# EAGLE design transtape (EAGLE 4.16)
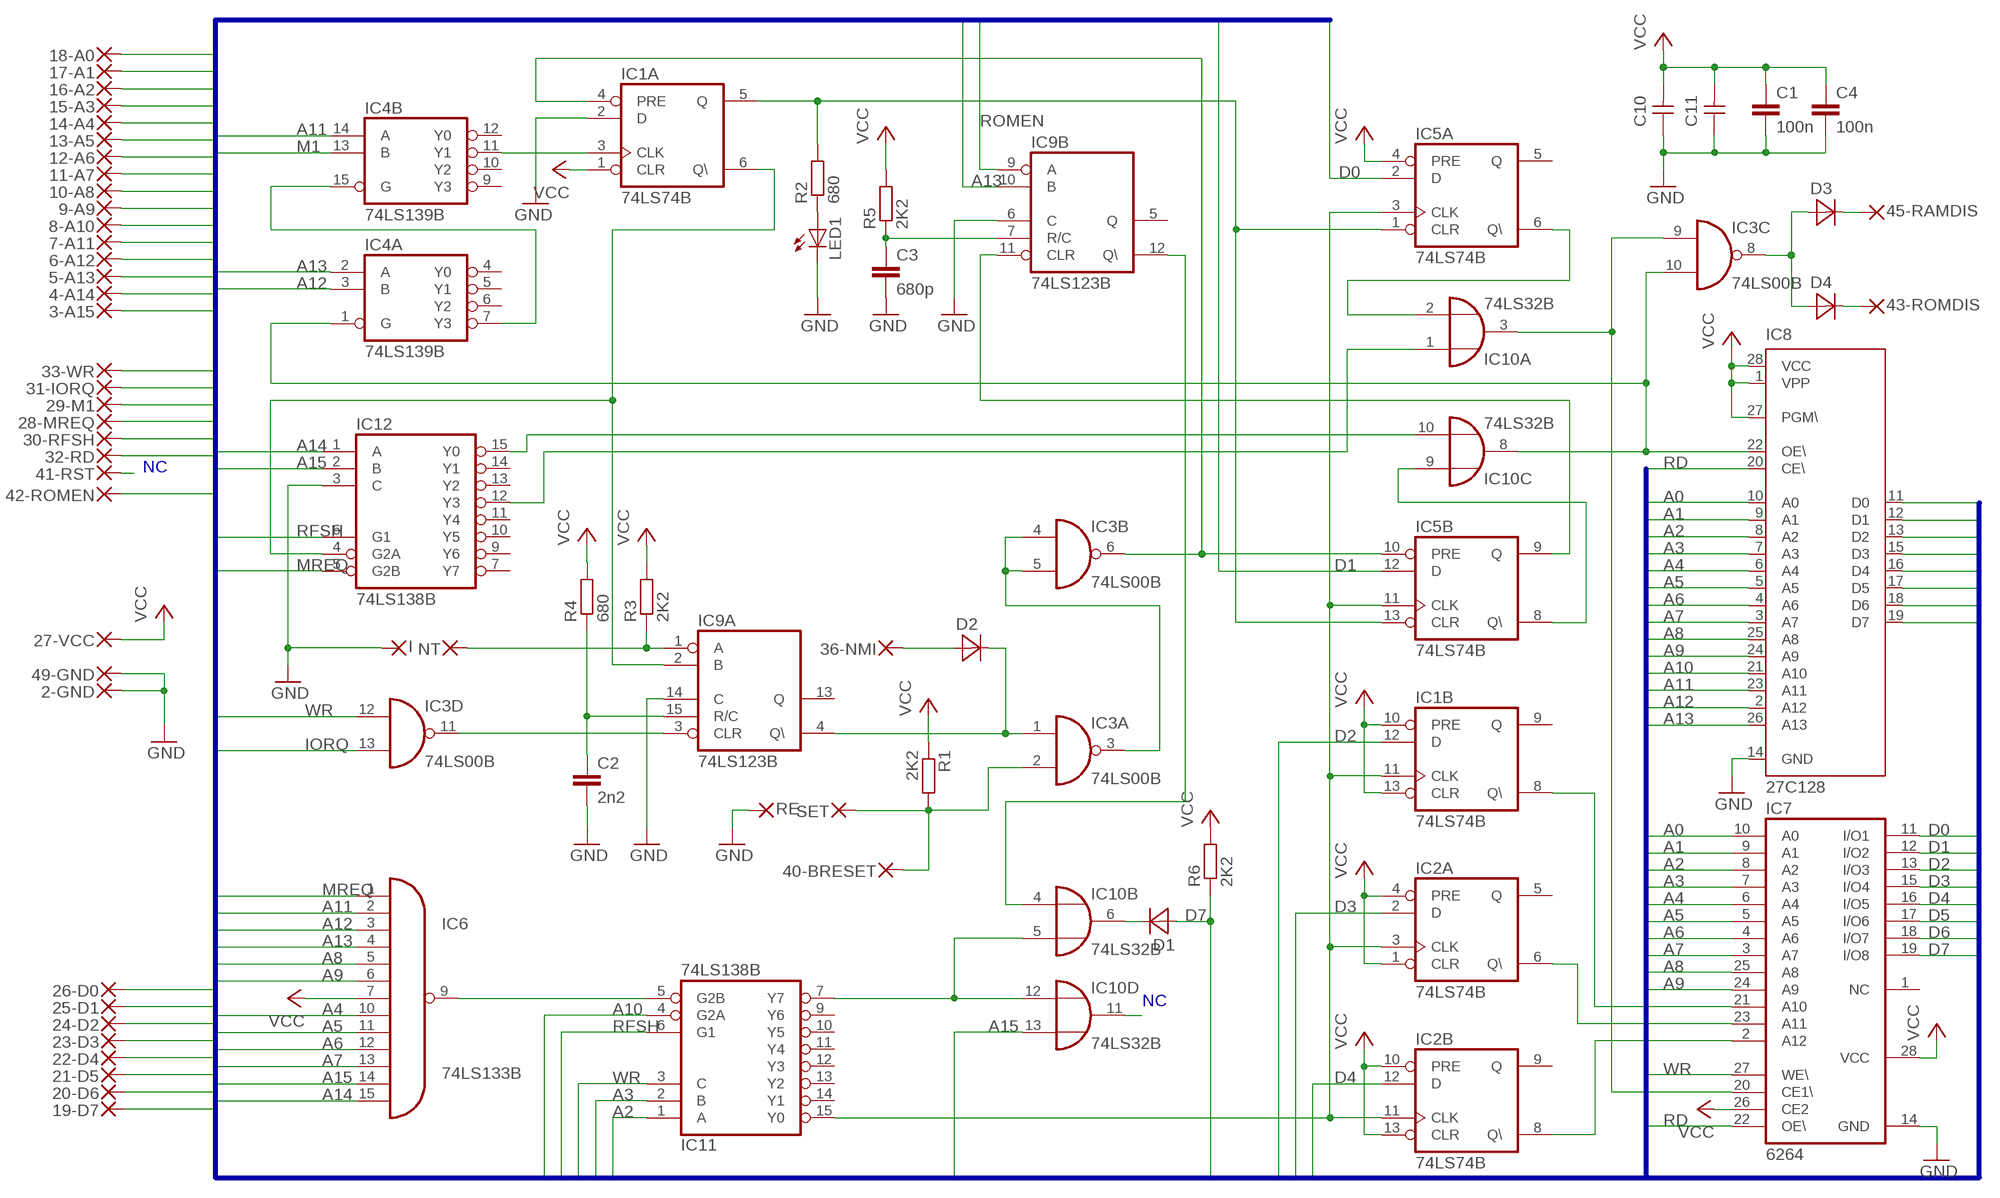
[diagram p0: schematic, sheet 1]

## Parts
2-GND  1,27-REDONDO0.8  [1,27/0,8-REDONDO]
3-A15  1,27-REDONDO0.8  [1,27/0,8-REDONDO]
4-A14  1,27-REDONDO0.8  [1,27/0,8-REDONDO]
5-A13  1,27-REDONDO0.8  [1,27/0,8-REDONDO]
6-A12  1,27-REDONDO0.8  [1,27/0,8-REDONDO]
7-A11  1,27-REDONDO0.8  [1,27/0,8-REDONDO]
8-A10  1,27-REDONDO0.8  [1,27/0,8-REDONDO]
9-A9  1,27-REDONDO0.8  [1,27/0,8-REDONDO]
10-A8  1,27-REDONDO0.8  [1,27/0,8-REDONDO]
11-A7  1,27-REDONDO0.8  [1,27/0,8-REDONDO]
12-A6  1,27-REDONDO0.8  [1,27/0,8-REDONDO]
13-A5  1,27-REDONDO0.8  [1,27/0,8-REDONDO]
14-A4  1,27-REDONDO0.8  [1,27/0,8-REDONDO]
15-A3  1,27-REDONDO0.8  [1,27/0,8-REDONDO]
16-A2  1,27-REDONDO0.8  [1,27/0,8-REDONDO]
17-A1  1,27-REDONDO0.8  [1,27/0,8-REDONDO]
18-A0  1,27-REDONDO0.8  [1,27/0,8-REDONDO]
19-D7  1,27-REDONDO0.8  [1,27/0,8-REDONDO]
20-D6  1,27-REDONDO0.8  [1,27/0,8-REDONDO]
21-D5  1,27-REDONDO0.8  [1,27/0,8-REDONDO]
22-D4  1,27-REDONDO0.8  [1,27/0,8-REDONDO]
23-D3  1,27-REDONDO0.8  [1,27/0,8-REDONDO]
24-D2  1,27-REDONDO0.8  [1,27/0,8-REDONDO]
25-D1  1,27-REDONDO0.8  [1,27/0,8-REDONDO]
26-D0  1,27-REDONDO0.8  [1,27/0,8-REDONDO]
27-VCC  1,27-REDONDO0.8  [1,27/0,8-REDONDO]
28-MREQ  1,27-REDONDO0.8  [1,27/0,8-REDONDO]
29-M1  1,27-REDONDO0.8  [1,27/0,8-REDONDO]
30-RFSH  1,27-REDONDO0.8  [1,27/0,8-REDONDO]
31-IORQ  1,27-REDONDO0.8  [1,27/0,8-REDONDO]
32-RD  1,27-REDONDO0.8  [1,27/0,8-REDONDO]
33-WR  1,27-REDONDO0.8  [1,27/0,8-REDONDO]
36-NMI  1,27-REDONDO0.8  [1,27/0,8-REDONDO]
40-BRESET  1,27-REDONDO0.8  [1,27/0,8-REDONDO]
41-RST  1,27-REDONDO0.8  [1,27/0,8-REDONDO]
42-ROMEN  1,27-REDONDO0.8  [1,27/0,8-REDONDO]
43-ROMDIS  1,27-REDONDO0.8  [1,27/0,8-REDONDO]
45-RAMDIS  1,27-REDONDO0.8  [1,27/0,8-REDONDO]
49-GND  1,27-REDONDO0.8  [1,27/0,8-REDONDO]
C1  100n  C-EU050-025X075  [C050-025X075]
C2  2n2  C-EU050-025X075  [C050-025X075]
C3  680p  C-EU050-025X075  [C050-025X075]
C4  100n  C-EU075-032X103  [C075-032X103]
C10  CAPNP-7,5  [C-7,5]
C11  CAPNP-7,5  [C-7,5]
D1  DIODE-5  [D-5]
D2  DIODE-7,5  [D-7,5]
D3  DIODE-7,5  [D-7,5]
D4  DIODE-7,5  [D-7,5]
I  1,27-OVALADO0.8  [1,27/0,8]
IC1  74LS74B  [DIL14-B]
IC2  74LS74B  [DIL14-B]
IC3  74LS00B  [DIL14-B]
IC4  74LS139B  [DIL16-B]
IC5  74LS74B  [DIL14-B]
IC6  74LS133B  [DIL16-B]
IC7  6264  4364CB  [DIL28-6B]
IC8  27C128  27128B  [DIL28-6B]
IC9  74LS123B  [DIL16-B]
IC10  74LS32B  [DIL14-B]
IC11  74LS138B  [DIL16-B]
IC12  74LS138B  [DIL16-B]
LED1  LED3MM  [LED3MM]
NT  1,27-OVALADO0.8  [1,27/0,8]
R1  2K2  R-EU_0207/10  [0207/10]
R2  680  R-EU_0207/10  [0207/10]
R3  2K2  R-EU_0207/10  [0207/10]
R4  680  R-EU_0207/10  [0207/10]
R5  2K2  R-EU_0207/10  [0207/10]
R6  2K2  R-EU_0207/7  [0207/7]
RE  1,27-OVALADO0.8  [1,27/0,8]
SET  1,27-OVALADO0.8  [1,27/0,8]

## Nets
A0: 18-A0.1(P) IC7.10(A0) IC8.10(A0)
A1: 17-A1.1(P) IC7.9(A1) IC8.9(A1)
A2: 16-A2.1(P) IC7.8(A2) IC8.8(A2) IC11.1(A)
A3: 15-A3.1(P) IC7.7(A3) IC8.7(A3) IC11.2(B)
A4: 14-A4.1(P) IC6.10(I7) IC7.6(A4) IC8.6(A4)
A5: 13-A5.1(P) IC6.11(I8) IC7.5(A5) IC8.5(A5)
A6: 12-A6.1(P) IC6.12(I9) IC7.4(A6) IC8.4(A6)
A7: 11-A7.1(P) IC6.13(I10) IC7.3(A7) IC8.3(A7)
A8: 10-A8.1(P) IC6.5(I4) IC7.25(A8) IC8.25(A8)
A9: 9-A9.1(P) IC6.6(I5) IC7.24(A9) IC8.24(A9)
A10: 8-A10.1(P) IC8.21(A10) IC11.4(G2A)
A11: 7-A11.1(P) IC4.14(B:A) IC6.2(I1) IC8.23(A11)
A12: 6-A12.1(P) IC4.3(A:B) IC6.3(I2) IC8.2(A12)
A13: 5-A13.1(P) IC4.2(A:A) IC6.4(I3) IC8.26(A13) IC9.10(B:B)
A14: 4-A14.1(P) IC6.15(I12) IC12.1(A)
A15: 3-A15.1(P) IC6.14(I11) IC10.13(D:I1) IC12.2(B)
BRESET: 40-BRESET.1(P) IC3.2(A:I1) R1.2 SET.1(P)
D0: 26-D0.1(P) IC5.2(A:D) IC7.11(I/O1) IC8.11(D0)
D1: 25-D1.1(P) IC5.12(B:D) IC7.12(I/O2) IC8.12(D1)
D2: 24-D2.1(P) IC1.12(B:D) IC7.13(I/O3) IC8.13(D2)
D3: 23-D3.1(P) IC2.2(A:D) IC7.15(I/O4) IC8.15(D3)
D4: 22-D4.1(P) IC2.12(B:D) IC7.16(I/O5) IC8.16(D4)
D5: 21-D5.1(P) IC7.17(I/O6) IC8.17(D5)
D6: 20-D6.1(P) IC7.18(I/O7) IC8.18(D6)
D7: 19-D7.1(P) D1.A IC7.19(I/O8) IC8.19(D7) R6.1
GND: 2-GND.1(P) 49-GND.1(P) C1.2 C2.2 C3.2 C4.2 C10.1 C11.1 I.1(P) IC1.2(A:D) IC7.14(GND) IC8.14(GND) IC9.6(B:C) IC9.14(A:C) IC12.3(C) LED1.K(C) RE.1(P)
IORQ: 31-IORQ.1(P) IC3.13(D:I1)
M1: 29-M1.1(P) IC4.13(B:B)
MREQ: 28-MREQ.1(P) IC6.1(I0) IC12.5(G2B)
N$5: IC3.10(C:I1) IC4.1(A:G) IC8.22(OE\) IC10.8(C:O)
N$12: 41-RST.1(P)
N$27: IC10.11(D:O)
N$33: IC10.1(A:I0) IC12.12(Y3)
N$34: IC1.6(A:Q\) IC9.2(A:B) IC12.4(G2A)
N$35: IC9.1(A:A) NT.1(P) R3.1
N$36: IC10.10(C:I1) IC12.15(Y0)
N$37: IC1.11(B:CLK) IC2.3(A:CLK) IC2.11(B:CLK) IC5.3(A:CLK) IC5.11(B:CLK) IC11.15(Y0)
N$38: IC6.9(O) IC11.5(G2B)
N$39: IC10.5(B:I1) IC10.12(D:I0) IC11.7(Y7)
N$40: IC5.8(B:Q\) IC10.9(C:I0)
N$41: IC5.6(A:Q\) IC10.2(A:I1)
N$42: IC3.9(C:I0) IC7.20(CE1\) IC10.3(A:O)
N$43: IC9.12(B:Q\) IC10.4(B:I0)
N$44: D1.C(K) IC10.6(B:O)
N$45: C2.1 IC9.15(A:R/C) R4.1
N$46: C3.1 IC9.7(B:R/C) R5.1
N$47: LED1.A R2.1
N$50: IC5.9(B:Q) IC9.11(B:CLR)
N$51: D2.2(K) IC3.1(A:I0) IC9.4(A:Q\)
N$52: IC3.11(D:O) IC9.3(A:CLR)
N$53: IC1.5(A:Q) IC5.1(A:CLR) IC5.13(B:CLR) R2.2
N$54: IC1.4(A:PRE) IC3.6(B:O) IC5.10(B:PRE)
N$57: IC1.3(A:CLK) IC4.11(B:Y1)
N$58: IC1.8(B:Q\) IC7.21(A10)
N$59: IC2.6(A:Q\) IC7.23(A11)
N$60: IC2.8(B:Q\) IC7.2(A12)
N$62: IC3.3(A:O) IC3.4(B:I0) IC3.5(B:I1)
N$64: D3.1(A) D4.1(A) IC3.8(C:O)
N$66: IC4.7(A:Y3) IC4.15(B:G)
N$72: 36-NMI.1(P) D2.1(A)
RAMDIS: 45-RAMDIS.1(P) D3.2(K)
RD: 32-RD.1(P) IC7.22(OE\) IC8.20(CE\)
RFSH: 30-RFSH.1(P) IC11.6(G1) IC12.6(G1)
ROMDIS: 43-ROMDIS.1(P) D4.2(K)
ROMEN: 42-ROMEN.1(P) IC9.9(B:A)
VCC: 27-VCC.1(P) C1.1 C4.1 C10.2 C11.2 IC1.1(A:CLR) IC1.10(B:PRE) IC1.13(B:CLR) IC2.1(A:CLR) IC2.4(A:PRE) IC2.10(B:PRE) IC2.13(B:CLR) IC5.4(A:PRE) IC6.7(I6) IC7.26(CE2) IC7.28(VCC) IC8.1(VPP) IC8.27(PGM\) IC8.28(VCC) R1.1 R3.2 R4.2 R5.2 R6.2
WR: 33-WR.1(P) IC3.12(D:I0) IC7.27(WE\) IC11.3(C)
Unconnected: IC1.9(B:Q) IC2.5(A:Q) IC2.9(B:Q) IC4.4(A:Y0) IC4.5(A:Y1) IC4.6(A:Y2) IC4.9(B:Y3) IC4.10(B:Y2) IC4.12(B:Y0) IC5.5(A:Q) IC7.1(NC) IC9.5(B:Q) IC9.13(A:Q) IC11.9(Y6) IC11.10(Y5) IC11.11(Y4) IC11.12(Y3) IC11.13(Y2) IC11.14(Y1) IC12.7(Y7) IC12.9(Y6) IC12.10(Y5) IC12.11(Y4) IC12.13(Y2) IC12.14(Y1)

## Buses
A[0..15],RD,WR,IORQ,M1,MREQ,RFSH,D[0..7],ROMEN

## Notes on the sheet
- NC
- NC

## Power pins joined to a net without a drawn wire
GND: IC1.7(P:GND) IC2.7(P:GND) IC3.7(P:GND) IC4.8(P:GND) IC5.7(P:GND) IC6.8(GND) IC9.8(P:GND) IC10.7(P:GND) IC11.8(GND) IC12.8(GND)
VCC: IC1.14(P:VCC) IC2.14(P:VCC) IC3.14(P:VCC) IC4.16(P:VCC) IC5.14(P:VCC) IC6.16(VCC) IC9.16(P:VCC) IC10.14(P:VCC) IC11.16(VCC) IC12.16(VCC)

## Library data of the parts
2-GND 3-A15 4-A14 5-A13 6-A12 7-A11 8-A10 9-A9 10-A8 11-A7 12-A6 13-A5 14-A4 15-A3 16-A2 17-A1 18-A0 19-D7 20-D6 21-D5 22-D4 23-D3 24-D2 25-D1 26-D0 27-VCC 28-MREQ 29-M1 30-RFSH 31-IORQ 32-RD 33-WR 36-NMI 40-BRESET 41-RST 42-ROMEN 43-ROMDIS 45-RAMDIS 49-GND = wirepad2:1,27-REDONDO
C1-C4 = rcl:C-EU: CAPACITOR, European symbol
C10 C11 = discrete2:CAPNP-7,5
D1 = discrete2:DIODE-5
D2-D4 = discrete2:DIODE-7,5
I NT RE SET = wirepad2:1,27-OVALADO
IC1 IC2 IC5 = 74xx-eu2:74*74: Dual D type positive edge triggered FLIP FLOP, preset and clear
IC3 = 74xx-eu2:74*00: Quad 2-input NAND gate
IC4 = 74xx-eu2:74*139: Dual 2-line to 4-line DECODER/DEMULTIPLEXER
IC6 = 74xx-eu2:74*133: 13-input NAND gate
IC7 = memory-nec:4364C: MEMORY
IC8 = microchip:27*128: CMOS EPROM 128 K (16 K x 8)
IC9 = 74xx-eu2:74*123: Retriggerable monostable MULTIVIBRATOR
IC10 = 74xx-eu2:74*32: Quad 2-input OR gate
IC11 IC12 = 74xx-eu2:74*138: 3-line to 8-line DECODER/DEMULTIPLEXER
LED1 = led:LED: LED
R1-R6 = rcl:R-EU_: RESISTOR, European symbol

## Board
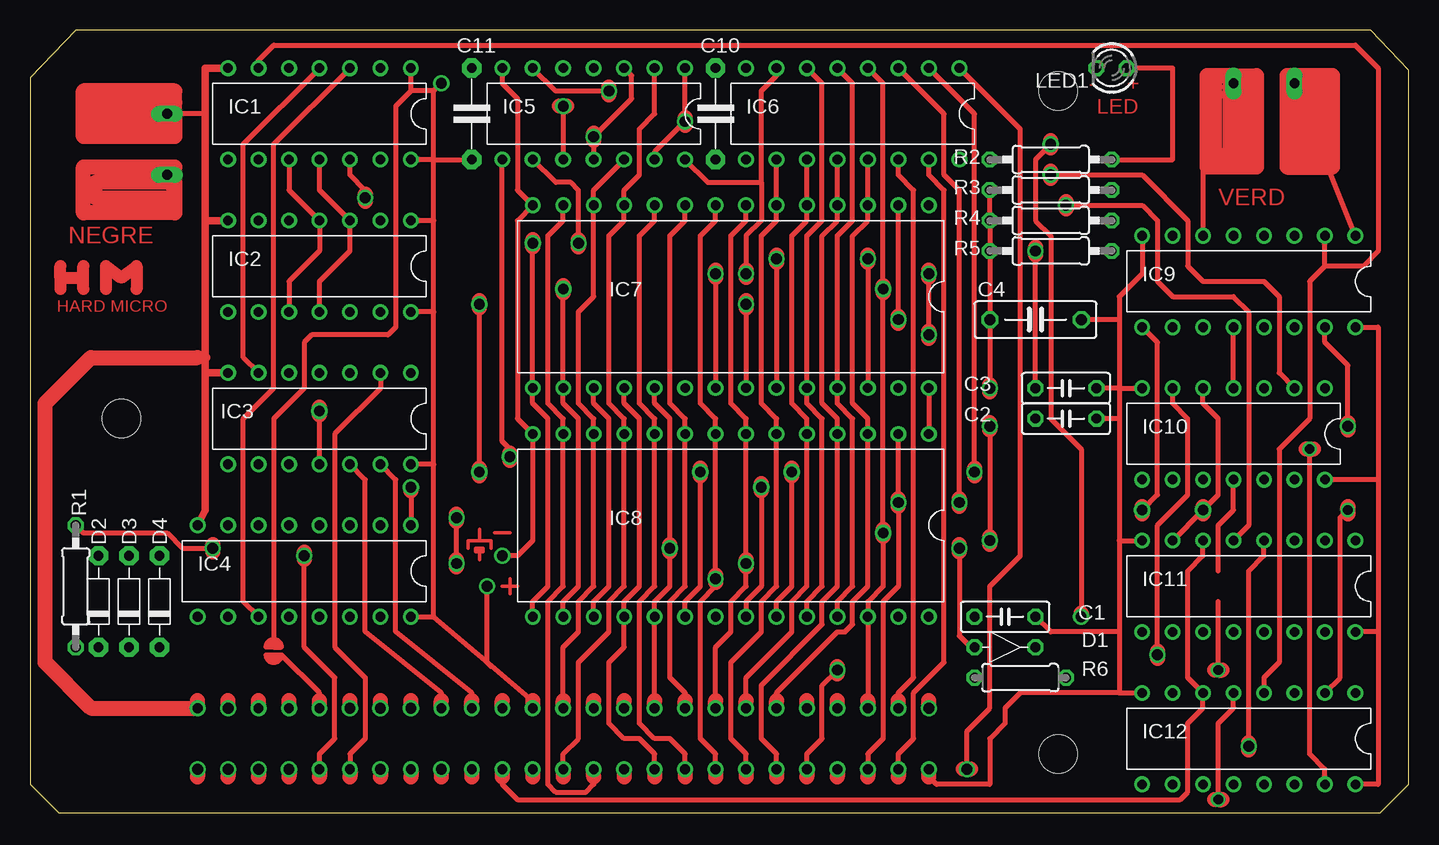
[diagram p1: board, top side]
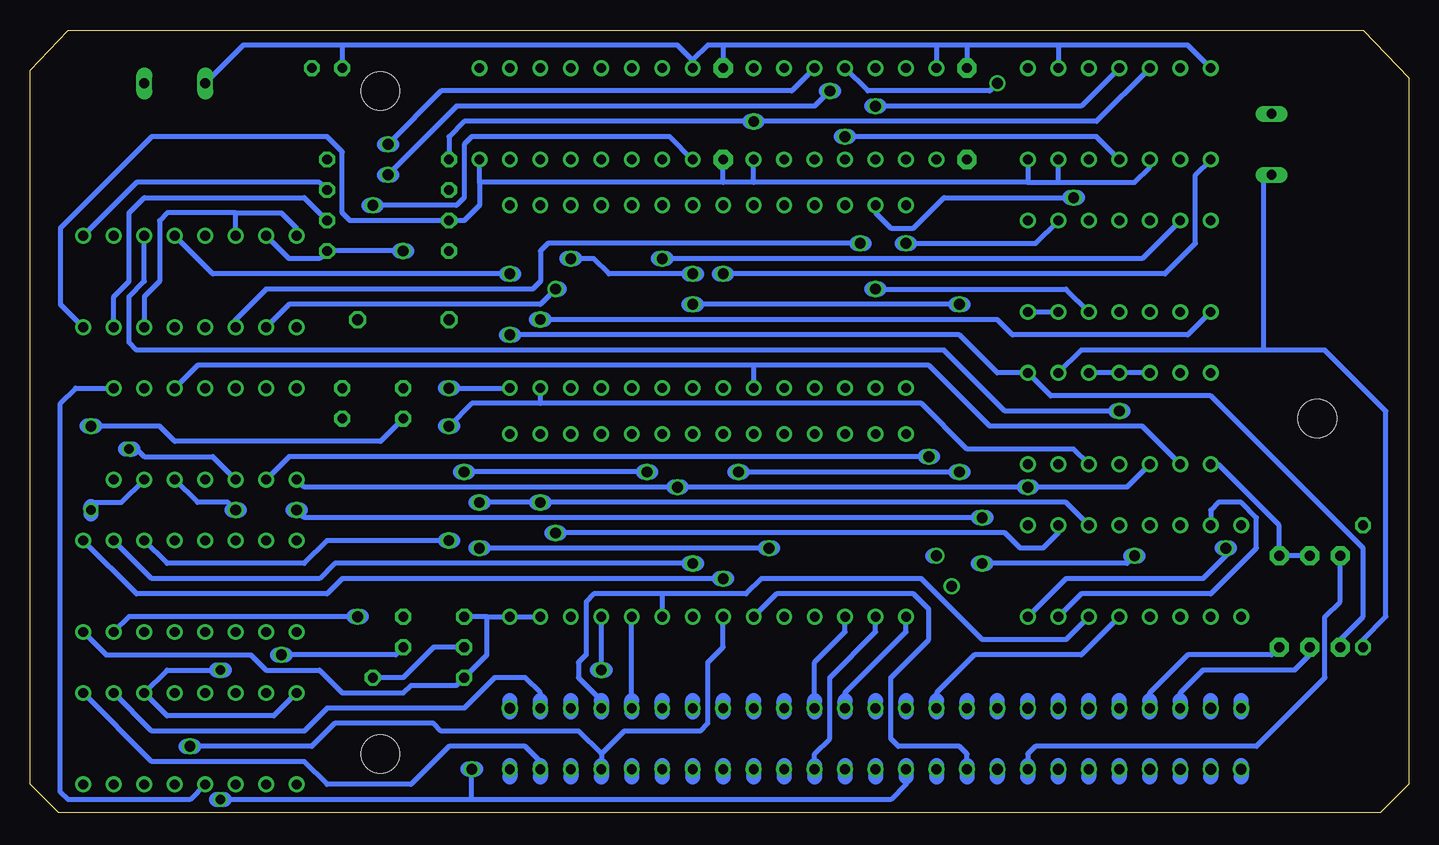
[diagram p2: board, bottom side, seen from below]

Size 114.94 x 65.24 mm. Coordinates in mm from the lower left corner, seen from the top.
Outline: 112.56,0 114.94,2.38 114.92,61.9 114.94,61.9 111.76,65.24 3.81,65.24 0,61.27 0.01,59.99 0,2.38 2.38,0 112.56,0
Copper layers (1*16): Top 0.035mm / dielectric 1.5mm / Bottom 0.035mm
Design rules "default": minimum track width 10mil, minimum drill 24mil, track to track 8mil, track to pad 8mil, pad to pad 8mil, via to via 8mil, smd to smd 8mil, copper to edge 40mil, drill to drill 8mil, minimum pad ring 10mil, minimum via ring 8mil, stop-mask expansion 4mil, vias tented up to drill 0mil, thermal gap 10mil
Holes 3.2 mm at 85.72,4.92 85.72,60.16 7.62,32.86

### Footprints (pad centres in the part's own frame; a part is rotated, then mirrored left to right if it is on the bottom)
1,27/0,8-REDONDO = drill 0.813 pad 1.27 round: 1 0,0
C050-025X075 = drill 0.813 octagon: 1 -2.54,0; 2 2.54,0
C075-032X103 = drill 0.914 octagon: 1 -3.81,0; 2 3.81,0
C-7,5 = drill 0.813 pad 1.6 octagon: 1 -3.81,0; 2 3.81,0
D-5 = drill 0.813 octagon: A -2.54,0; C 2.54,0
D-7,5 = drill 0.813 pad 1.6 octagon: 1 -3.81,0; 2 3.81,0
1,27/0,8 = drill 0.813 long: 1 -1.27,1.27
DIL14-B = drill 0.813 round: 1 -7.62,-3.81; 2 -5.08,-3.81; 3 -2.54,-3.81; 4 0,-3.81; 5 2.54,-3.81; 6 5.08,-3.81; 7 7.62,-3.81; 8 7.62,3.81; 9 5.08,3.81; 10 2.54,3.81; 11 0,3.81; 12 -2.54,3.81; 13 -5.08,3.81; 14 -7.62,3.81
DIL16-B = drill 0.813 round: 1 -8.89,-3.81; 2 -6.35,-3.81; 3 -3.81,-3.81; 4 -1.27,-3.81; 5 1.27,-3.81; 6 3.81,-3.81; 7 6.35,-3.81; 8 8.89,-3.81; 9 8.89,3.81; 10 6.35,3.81; 11 3.81,3.81; 12 1.27,3.81; 13 -1.27,3.81; 14 -3.81,3.81; 15 -6.35,3.81; 16 -8.89,3.81
DIL28-6B = drill 0.8 round: 1 -16.51,-7.62; 2 -13.97,-7.62; 3 -11.43,-7.62; 4 -8.89,-7.62; 5 -6.35,-7.62; 6 -3.81,-7.62; 7 -1.27,-7.62; 8 1.27,-7.62; 9 3.81,-7.62; 10 6.35,-7.62; 11 8.89,-7.62; 12 11.43,-7.62; 13 13.97,-7.62; 14 16.51,-7.62; 15 16.51,7.62; 16 13.97,7.62; 17 11.43,7.62; 18 8.89,7.62; 19 6.35,7.62; 20 3.81,7.62; 21 1.27,7.62; 22 -1.27,7.62; 23 -3.81,7.62; 24 -6.35,7.62; 25 -8.89,7.62; 26 -11.43,7.62; 27 -13.97,7.62; 28 -16.51,7.62
LED3MM = drill 0.813 octagon: A -1.27,0; K 1.27,0
0207/10 = drill 0.813 octagon: 1 -5.08,0; 2 5.08,0
0207/7 = drill 0.813 octagon: 1 -3.81,0; 2 3.81,0

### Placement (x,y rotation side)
2-GND  74.93,3.65 180 top
3-A15  72.39,8.73 0 top
4-A14  72.39,3.65 180 top
5-A13  69.85,8.73 0 top
6-A12  69.85,3.65 180 top
7-A11  67.31,8.73 0 top
8-A10  67.31,3.65 180 top
9-A9  64.77,8.73 0 top
10-A8  64.77,3.65 180 top
11-A7  62.23,8.73 0 top
12-A6  62.23,3.65 180 top
13-A5  59.69,8.73 0 top
14-A4  59.69,3.65 180 top
15-A3  57.15,8.73 0 top
16-A2  57.15,3.65 180 top
17-A1  54.61,8.73 0 top
18-A0  54.61,3.65 180 top
19-D7  52.07,8.73 0 top
20-D6  52.07,3.65 180 top
21-D5  49.53,8.73 0 top
22-D4  49.53,3.65 180 top
23-D3  46.99,8.73 0 top
24-D2  46.99,3.65 180 top
25-D1  44.45,8.73 0 top
26-D0  44.45,3.65 180 top
27-VCC  41.91,8.73 0 top
28-MREQ  41.91,3.65 180 top
29-M1  39.37,8.73 0 top
30-RFSH  39.37,3.65 180 top
31-IORQ  36.83,8.73 0 top
32-RD  36.83,3.65 180 top
33-WR  34.29,8.73 0 top
36-NMI  31.75,3.65 180 top
40-BRESET  26.67,3.65 180 top
41-RST  24.13,8.73 0 top
42-ROMEN  24.13,3.65 180 top
43-ROMDIS  21.59,8.73 0 top
45-RAMDIS  19.05,8.73 0 top
49-GND  13.97,8.73 0 top
C1  81.28,16.35 0 top
C2  86.36,32.86 0 top
C3  86.36,35.4 0 top
C4  83.82,41.11 0 top
C10  57.15,58.26 270 top
C11  36.83,58.26 270 top
D1  81.28,13.81 0 top
D2  5.71,17.62 270 top
D3  8.26,17.62 270 top
D4  10.79,17.62 270 top
I  101.6,59.52 0 top
IC1  24.13,58.26 180 top
IC2  24.13,45.55 180 top
IC3  24.13,32.86 180 top
IC4  22.86,20.16 180 top
IC5  46.99,58.26 180 top
IC6  68.58,58.26 180 top
IC7  58.42,43.02 180 top
IC8  58.42,23.96 180 top
IC9  101.6,44.29 180 top
IC10  100.33,31.59 180 top
IC11  101.6,18.89 180 top
IC12  101.6,6.18 180 top
LED1  90.17,62.06 180 top
NT  106.68,59.52 0 top
R1  3.81,18.89 270 top
R2  85.09,54.45 180 top
R3  85.09,51.91 180 top
R4  85.09,49.37 180 top
R5  85.09,46.83 180 top
R6  82.55,11.27 180 top
RE  12.7,59.52 90 top
SET  12.7,54.45 90 top

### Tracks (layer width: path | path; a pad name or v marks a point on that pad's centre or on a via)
A0
  Top 0.406: IC7.10 52.07,49.37 50.8,48.09 50.8,34.12 52.07,32.86 IC8.10 52.07,18.89 50.8,17.62 50.8,7.46 52.07,6.18 53.34,6.18 54.61,4.92 18-A0.1
  Top 1.27: 18-A0.1 54.61,3.01
  Bottom 1.27: 54.61,3.96 18-A0.1 54.61,3.01
A1
  Top 0.406: IC7.9 54.61,49.37 53.34,48.09 53.34,34.12 54.61,32.86 IC8.9 54.61,18.89 53.34,17.62 53.34,11.27 54.61,10 54.61,9.36
  Top 1.27: 17-A1.1 54.61,9.36
  Bottom 1.27: 54.61,9.36 17-A1.1 54.61,8.41
A2  (via drill 0.9)
  Top 0.406: 16-A2.1 57.15,4.92 55.88,6.18 55.88,17.62 57.15,18.89 v57.15,19.52 | IC7.8 57.15,49.37 55.88,48.09 55.88,34.12 57.15,32.86 IC8.8 57.15,19.84
  Top 1.27: 16-A2.1 57.15,3.01 | 57.15,19.84 v57.15,19.52 57.15,19.2
  Bottom 0.406: IC11.1 106.05,18.25 90.17,18.25 88.9,19.52 57.47,19.52
  Bottom 1.27: 57.15,3.96 16-A2.1 57.15,3.01 | 56.83,19.52 v57.15,19.52 57.47,19.52
A3  (via drill 0.9)
  Top 0.406: 57.15,9.36 57.15,13.81 58.42,15.08 58.42,17.62 59.69,18.89 59.69,20.47 v59.69,20.79 | 59.69,21.11 IC8.7 59.69,32.86 58.42,34.12 58.42,48.09 59.69,49.37 IC7.7
  Top 1.27: 15-A3.1 57.15,9.36 | v59.69,20.79 59.69,21.11 59.69,20.47
  Bottom 0.406: IC11.2 104.78,19.52 90.81,19.52 89.53,20.79 60.01,20.79 v59.69,20.79
  Bottom 1.27: 57.15,9.36 15-A3.1 57.15,8.41 | 59.37,20.79 v59.69,20.79 60.01,20.79
A4
  Top 0.406: IC6.10 IC7.6 62.23,49.37 60.96,48.09 60.96,34.12 62.23,32.86 IC8.6 62.23,18.89 60.96,17.62 60.96,15.08 58.42,12.54 58.42,6.18 59.69,4.92 14-A4.1
  Top 1.27: 14-A4.1 59.69,3.01
  Bottom 1.27: 59.69,3.96 14-A4.1 59.69,3.01
A5
  Top 0.406: IC6.11 IC7.5 64.77,49.37 63.5,48.09 63.5,34.12 64.77,32.86 IC8.5 64.77,18.89 63.5,17.62 63.5,15.08 59.69,11.27 59.69,9.36
  Top 1.27: 13-A5.1 59.69,9.36
  Bottom 1.27: 59.69,8.41 13-A5.1 59.69,9.36
A6
  Top 0.406: IC6.12 IC7.4 67.31,49.37 66.04,48.09 66.04,34.12 67.31,32.86 IC8.4 67.31,18.89 66.04,17.62 66.04,15.71 60.96,10.63 60.96,6.18 62.23,4.92 12-A6.1
  Top 1.27: 12-A6.1 62.23,3.01
  Bottom 1.27: 62.23,3.96 12-A6.1 62.23,3.01
A7
  Top 0.406: IC6.13 IC7.3 69.85,49.37 68.58,48.09 68.58,34.12 69.85,32.86 IC8.3 69.85,18.89 68.58,17.62 68.58,15.71 67.94,15.08 67.31,15.08 62.23,10 62.23,9.36
  Top 1.27: 11-A7.1 62.23,9.36
  Bottom 1.27: 62.23,8.41 11-A7.1 62.23,9.36
A8  (via drill 0.9)
  Top 0.406: IC6.5 68.58,60.8 68.58,49.37 67.31,48.09 IC7.25 67.31,34.12 68.58,32.86 68.58,18.89 67.31,17.62 IC8.25 | 10-A8.1 64.77,4.92 66.04,6.18 66.04,10.63 v67.31,11.9
  Top 1.27: 10-A8.1 64.77,3.01 | 67.31,12.22 v67.31,11.9 67.31,11.58
  Bottom 0.406: v67.31,11.9 IC8.25
  Bottom 1.27: 64.77,3.01 10-A8.1 64.77,3.96 | 67.63,11.9 v67.31,11.9 66.99,11.9
A9
  Top 0.406: IC6.6 66.04,60.8 66.04,49.37 64.77,48.09 IC7.24 64.77,34.12 66.04,32.86 66.04,18.89 64.77,17.62 IC8.24
  Top 1.27: 9-A9.1 64.77,9.36
  Bottom 0.406: 9-A9.1 IC8.24
  Bottom 1.27: 64.77,8.41 9-A9.1 64.77,9.36
A10  (via drill 0.9)
  Top 0.406: 101.6,5.87 101.6,20.16 102.87,21.43 IC11.4
  Top 1.27: 8-A10.1 67.31,3.01 | v101.6,5.55 101.6,5.87 101.6,5.23
  Bottom 0.406: 67.31,4.92 67.31,3.96 | 67.31,4.92 69.22,6.82 80.64,6.82 81.28,7.46 89.53,7.46 91.44,5.55 101.28,5.55 | IC8.21 57.15,13.81 58.42,12.54 58.42,7.46 59.05,6.82 65.41,6.82 67.31,4.92
  Bottom 1.27: 67.31,3.01 8-A10.1 67.31,3.96 | v101.6,5.55 101.28,5.55 101.92,5.55
A11  (via drill 0.9)
  Top 0.406: IC6.2 78.74,58.26 78.74,28.73 | 63.5,28.09 63.5,18.89 62.23,17.62 IC8.23
  Top 1.27: 7-A11.1 67.31,9.36 | 63.5,28.73 v63.5,28.41 63.5,28.09 | v78.74,28.41 78.74,28.73 78.74,28.09
  Bottom 0.406: 63.82,28.41 78.42,28.41 | 62.23,18.25 IC8.23 | 62.23,18.25 67.94,18.25 68.58,17.62 68.58,13.17 69.22,12.54 69.22,11.27 67.31,9.36 | IC4.14 28.57,14.44 35.56,14.44 40.64,19.52 53.98,19.52 55.24,18.25 62.23,18.25
  Bottom 1.27: 67.31,8.41 7-A11.1 67.31,9.36 | v78.74,28.41 78.42,28.41 79.06,28.41 | 63.18,28.41 v63.5,28.41 63.82,28.41
A12  (via drill 0.9)
  Top 0.406: IC6.3 76.2,58.26 76.2,53.18 77.47,51.91 77.47,26.19 | 72.39,26.19 IC8.2 | v72.39,25.87 72.39,25.55 72.39,18.89 71.12,17.62 71.12,6.18 69.85,4.92 6-A12.1
  Top 1.27: 6-A12.1 69.85,3.01 | v72.39,25.87 72.39,26.19 72.39,25.55 | v77.47,25.87 77.47,26.19 77.47,25.55
  Bottom 0.406: v72.39,25.87 72.71,25.87 77.15,25.87 | IC4.3 28.57,25.87 72.07,25.87
  Bottom 1.27: 69.85,3.01 6-A12.1 69.85,3.96 | v77.47,25.87 77.15,25.87 77.79,25.87 | v72.39,25.87 72.07,25.87 72.71,25.87
A13  (via drill 0.9)
  Top 0.406: 71.12,23.65 71.12,43.33 v71.12,43.65 | 71.12,43.97 71.12,60.8 IC6.4 | 69.85,9.36 IC8.26 69.85,17.62 71.12,18.89 71.12,23.01 v71.12,23.33
  Top 1.27: 69.85,9.36 5-A13.1 | v71.12,43.65 71.12,43.97 71.12,43.33 | v71.12,23.33 71.12,23.65 71.12,23.01
  Bottom 0.406: IC9.10 93.34,42.38 72.39,42.38 v71.12,43.65 | IC4.2 29.21,23.33 30.48,22.06 32.38,22.06 33.66,23.33 70.8,23.33
  Bottom 1.27: 69.85,8.41 5-A13.1 69.85,9.36 | 71.44,23.33 v71.12,23.33 70.8,23.33 | v71.12,43.65 70.8,43.65
A14
  Top 0.406: IC6.15 74.93,53.18 76.2,51.91 76.2,12.54 73.66,10 73.66,6.18 72.39,4.92 4-A14.1
  Top 1.27: 4-A14.1 72.39,3.01
  Bottom 0.406: 4-A14.1 72.39,4.28 73.66,5.55 80.01,5.55 83.19,2.38 90.17,2.38 92.08,4.28 104.78,4.28 IC12.1
  Bottom 1.27: 72.39,3.01 4-A14.1 72.39,3.96
A15  (via drill 0.8)
  Top 0.406: IC12.2 109.22,11.27 109.22,24.6 v109.86,25.23 | IC6.14 72.39,53.18 73.66,51.91 73.66,11.27 72.39,10 72.39,9.36
  Top 1.27: 109.86,25.55 v109.86,25.23 109.86,24.92 | 3-A15.1 72.39,9.36
  Bottom 0.406: 3-A15.1 72.39,10 73.66,11.27 76.2,11.27 78.74,8.73 90.17,8.73 92.08,6.82 104.78,6.82 IC12.2 | v109.86,25.23 109.86,25.87 107.31,25.87 IC10.13
  Bottom 1.27: 72.39,9.36 3-A15.1 72.39,8.41 | 109.86,25.55 v109.86,25.23 109.86,24.92
BRESET
  Top 0.406: IC3.2 29.21,35.4 25.4,31.59 25.4,13.81 27.94,11.27 27.94,6.18 26.67,4.92 40-BRESET.1
  Top 1.27: 40-BRESET.1 26.67,3.01 | SET.1 12.06,51.91 12.06,52.54 | 12.06,52.54 12.06,53.81 4.45,53.81 4.45,50 12.06,50 12.06,52.54 | 12.06,52.54 5.4,52.54 5.4,51.27 11.75,51.27
  Bottom 0.406: SET.1 12.06,53.18 12.06,38.57 | 12.06,38.57 27.3,38.57 IC3.2 | R1.2 3.81,14.44 1.91,16.35 1.91,33.49 6.99,38.57 12.06,38.57
  Bottom 1.27: 26.67,3.96 40-BRESET.1 26.67,3.01
D0
  Top 0.406: IC5.2 52.07,58.26 50.8,56.98 50.8,53.18 49.53,51.91 IC7.11 49.53,49.37 48.26,48.09 48.26,34.12 49.53,32.86 IC8.11 49.53,18.89 48.26,17.62 48.26,15.08 45.72,12.54 45.72,6.18 44.45,4.92 26-D0.1
  Top 1.27: 26-D0.1 44.45,3.01
  Bottom 1.27: 44.45,3.96 26-D0.1 44.45,3.01
D1
  Top 0.406: IC5.12 46.99,51.91 IC7.12 46.99,43.02 45.72,41.74 45.72,34.12 46.99,32.86 IC8.12 46.99,18.89 45.72,17.62 45.72,15.08 44.45,13.81 44.45,9.36
  Top 1.27: 25-D1.1 44.45,9.36
  Bottom 1.27: 44.45,8.41 25-D1.1 44.45,9.36
D2  (via drill 0.9)
  Top 0.406: IC7.13 44.45,49.37 43.18,48.09 43.18,34.12 44.45,32.86 IC8.13 44.45,18.89 43.18,17.62 43.18,2.38 43.81,1.74 46.35,1.74 46.99,2.38 46.99,3.01 | IC1.12 26.67,53.18 27.94,51.91 27.94,51.59
  Top 1.27: 46.99,3.01 24-D2.1 | v27.94,51.27 27.94,51.59 27.94,50.95
  Bottom 0.406: 28.26,51.27 38.73,51.27 41.27,48.73 43.18,48.73 44.45,50 IC7.13
  Bottom 1.27: 46.99,3.01 24-D2.1 46.99,3.96 | 27.62,51.27 v27.94,51.27 28.26,51.27
D3  (via drill 0.9)
  Top 0.406: IC8.15 41.91,17.62 43.18,18.89 43.18,32.86 41.91,34.12 IC7.15 41.91,47.14
  Top 1.27: 23-D3.1 46.99,9.36 | 41.91,47.78 v41.91,47.46 41.91,47.14
  Bottom 0.406: IC8.15 41.91,15.08 46.99,10 23-D3.1 | IC2.2 31.11,47.46 41.59,47.46
  Bottom 1.27: 46.99,8.41 23-D3.1 46.99,9.36 | v41.91,47.46 41.59,47.46 42.23,47.46
D4  (via drill 0.9)
  Top 0.406: IC8.16 44.45,17.62 45.72,18.89 45.72,32.86 44.45,34.12 IC7.16 44.45,43.33
  Top 1.27: 22-D4.1 49.53,3.01 | 44.45,43.97 v44.45,43.65 44.45,43.33
  Bottom 0.406: IC8.16 44.45,15.08 48.26,11.27 48.26,6.18 49.53,4.92 22-D4.1 | IC2.12 28.57,43.65 44.13,43.65
  Bottom 1.27: 22-D4.1 49.53,3.33 | 22-D4.1 49.53,3.96 | 22-D4.1 49.53,3.01 | 44.77,43.65 v44.45,43.65 44.13,43.65
D5
  Top 0.406: IC7.17 46.99,34.12 48.26,32.86 48.26,18.89 46.99,17.62 IC8.17
  Top 1.27: 21-D5.1 49.53,9.36
  Bottom 0.406: IC8.17 46.99,15.08 49.53,12.54 21-D5.1
  Bottom 1.27: 49.53,8.41 21-D5.1 49.53,9.36
D6
  Top 0.406: IC7.18 49.53,34.12 50.8,32.86 50.8,18.89 49.53,17.62 IC8.18 49.53,13.81 48.26,12.54 48.26,7.46 49.53,6.18 50.8,6.18 52.07,4.92 20-D6.1
  Top 1.27: 20-D6.1 52.07,3.01
  Bottom 1.27: 52.07,3.01 20-D6.1 52.07,3.96
D7  (via drill 0.9)
  Top 0.406: IC7.19 52.07,34.12 53.34,32.86 53.34,22.38 | 52.07,9.36 IC8.19 52.07,17.62 53.34,18.89 53.34,21.74 v53.34,22.06 | D1.A 78.42,13.81 77.47,14.76 77.47,21.74
  Top 1.27: 19-D7.1 52.07,9.36 | 77.47,22.38 v77.47,22.06 77.47,21.74 | v53.34,22.06 53.34,22.38 53.34,21.74
  Bottom 0.406: D1.A 81.28,13.81 83.82,11.27 R6.1 | 53.66,22.06 77.15,22.06
  Bottom 1.27: 52.07,8.41 19-D7.1 52.07,9.36 | 77.79,22.06 v77.47,22.06 77.15,22.06 | 53.02,22.06 v53.34,22.06 53.66,22.06
GND  (via drill 0.8, 0.9)
  Top 0.406: 74.93,3.01 75.56,2.38 80.01,2.38 80.01,6.18 81.28,7.46 81.28,8.73 82.55,10 90.81,10 | 90.81,10 IC12.8 | 90.81,15.08 90.81,10 | 90.81,22.7 90.81,15.08 | IC9.6 97.79,58.26 100.01,60.48 I.1 | C1.2 85.09,15.08 90.81,15.08 | IC9.8 92.71,44.92 90.81,43.02 90.81,41.11 | 90.81,41.11 90.81,35.4 | 90.81,35.4 IC10.7 | 90.81,22.7 IC11.8 | 90.81,35.4 90.81,32.86 | 90.81,32.86 90.81,22.7 | IC5.7 39.37,60.8 40.64,59.52 40.64,51.91 IC7.14 40.64,49.37 40.64,32.86 IC8.14 41.91,22.7 40.64,21.43 v39.37,21.43 | 90.81,32.86 C2.2 | 90.81,35.4 C3.2 | 14.61,58.26 12.06,58.26 | v99.06,11.9 99.06,17.62 | 90.81,41.11 C4.2
  Top 0.61: 14.61,36.66 14.61,37.94 14.61,49.37 | 14.61,36.66 IC3.7 | IC4.8 14.61,25.23 14.61,36.66 | IC1.7 14.61,62.06 14.61,58.26 14.61,49.37 | 14.61,49.37 IC2.7
  Top 0.813: 13.97,37.94 14.61,37.94
  Top 1.27: 13.97,37.94 5.08,37.94 1.27,34.12 1.27,12.54 5.08,8.73 49-GND.1 13.97,9.36 | 74.93,3.01 2-GND.1 | 98.74,11.9 v99.06,11.9 99.38,11.9 | 12.06,58.26 RE.1 | 12.06,58.26 12.06,60.16 4.45,60.16 4.45,56.35 12.06,56.35 12.06,58.26 | 12.06,58.26 12.06,59.21 5.4,59.21 5.4,57.3 11.43,57.3 RE.1 | RE.1 6.03,58.26 | I.1 100.33,61.43 98.74,61.43 | 98.74,61.43 98.11,61.43 98.11,53.81 102.23,53.81 102.23,61.43 98.74,61.43 | 98.74,61.43 98.74,54.76 101.28,54.76 101.28,60.48 100.01,60.48 100.01,54.45
  Bottom 0.406: IC12.8 94.61,8.09 103.5,8.09 IC12.3 103.5,11.9 99.38,11.9 | IC1.7 18.41,63.97 29.21,63.97 | 29.21,63.97 IC1.2 | 29.21,63.97 36.83,63.97 | 36.83,63.97 39.37,63.97 | 39.37,63.97 IC5.7 | 39.37,63.97 57.15,63.97 | 57.15,63.97 58.42,63.97 59.69,62.7 | 88.9,63.97 LED1.K | I.1 97.16,63.97 88.9,63.97 | 57.15,63.97 C10.1 | 36.83,63.97 C11.1 | IC9.8 92.71,48.73 93.98,50 97.79,50 | IC9.6 97.79,50 | IC9.14 105.41,43.02 104.14,44.29 104.14,49.37 103.5,50 97.79,50 | IC6.8 59.69,62.7 | 59.69,62.7 60.96,63.97 88.9,63.97
  Bottom 1.27: 13.97,9.36 49-GND.1 13.97,8.41 | 74.93,3.01 2-GND.1 74.93,3.96 | 98.74,11.9 v99.06,11.9 99.38,11.9 | v39.37,21.43 39.69,21.43
IORQ
  Top 0.406: IC3.13 30.48,27.78 30.48,15.08 36.83,10 31-IORQ.1
  Top 1.27: 31-IORQ.1 36.83,9.36
  Bottom 1.27: 36.83,8.41 31-IORQ.1 36.83,9.36
M1
  Top 1.27: 29-M1.1 39.37,9.36
  Bottom 0.406: IC4.13 27.3,13.17 36.2,13.17 39.37,10 29-M1.1
  Bottom 1.27: 39.37,8.41 29-M1.1 39.37,9.36
MREQ  (via drill 0.8, 0.9)
  Top 0.406: v99.06,1.1 99.06,7.46 100.33,8.73 IC12.5 | IC6.1 82.55,56.98 82.55,21.43 80.01,18.89 80.01,8.73 78.11,6.82 v78.11,3.65
  Top 1.27: 28-MREQ.1 41.91,3.01 | 98.74,1.1 v99.06,1.1 99.38,1.1 | 77.79,3.65 v78.11,3.65 78.42,3.65
  Bottom 0.406: 78.11,1.1 43.18,1.1 41.91,2.38 28-MREQ.1 | 78.11,1.1 98.74,1.1 | 78.11,1.1 v78.11,3.65
  Bottom 1.27: 77.79,3.65 v78.11,3.65 78.42,3.65 | 99.38,1.1 v99.06,1.1 98.74,1.1 | 41.91,3.96 28-MREQ.1 41.91,3.01
N$2  (via drill 0.9)
  Top 1.27: v74.93,8.73 74.93,9.36
  Bottom 1.27: 74.93,9.36 v74.93,8.73 74.93,8.41
N$4  (via drill 0.9)
  Top 1.27: v34.29,3.65 34.29,3.01
  Bottom 0.406: 34.29,4.28 34.29,3.96 v34.29,3.65
  Bottom 1.27: 34.29,3.96 v34.29,3.65 34.29,3.01
N$5  (via drill 0.9)
  Top 0.406: v60.96,27.14 60.96,26.82 60.96,18.89 59.69,17.62 IC8.22 | 31.75,26.82 IC4.1
  Top 1.27: v31.75,27.14 31.75,26.82 | 60.96,27.46 v60.96,27.14 60.96,26.82
  Bottom 0.406: IC10.8 92.08,27.14 61.28,27.14 v60.96,27.14 | v31.75,27.14 32.07,27.14 60.64,27.14 | IC3.10 23.5,27.14 31.43,27.14
  Bottom 1.27: v60.96,27.14 60.64,27.14 61.28,27.14 | v31.75,27.14 31.43,27.14 32.07,27.14
N$8  (via drill 0.9)
  Top 1.27: v31.75,8.73 31.75,9.36
  Bottom 1.27: 31.75,9.36 v31.75,8.73 31.75,8.41
N$9  (via drill 0.9)
  Top 1.27: v29.21,3.65 29.21,3.01
  Bottom 0.406: 29.21,4.28 29.21,3.96 v29.21,3.65
  Bottom 1.27: 29.21,3.96 v29.21,3.65 29.21,3.01
N$10  (via drill 0.9)
  Top 1.27: v29.21,8.73 29.21,9.36
  Bottom 1.27: 29.21,9.36 v29.21,8.73 29.21,8.41
N$11  (via drill 0.9)
  Top 1.27: v26.67,8.73 26.67,9.36
  Bottom 1.27: 26.67,9.36 v26.67,8.73 26.67,8.41
N$12
  Top 0.406: 24.13,9.36 24.13,10 20.95,13.17 | 19.68,13.17 20.32,13.17 | 19.68,13.17 arc90 20.32,12.54 | 20.32,12.54 arc90 20.95,13.17 | 19.68,13.17 20.32,12.54 | 20.32,12.54 20.95,13.17 | 20.32,13.17 20.95,13.17 | 20.32,13.17 20.32,12.54
  Top 1.27: 41-RST.1 24.13,9.36
  Bottom 1.27: 24.13,8.41 41-RST.1 24.13,9.36
N$13  (via drill 0.9)
  Top 1.27: v21.59,3.65 21.59,3.01
  Bottom 0.406: 21.59,4.28 21.59,3.96 v21.59,3.65
  Bottom 1.27: 21.59,3.96 v21.59,3.65 21.59,3.01
N$14  (via drill 0.9)
  Top 1.27: v19.05,3.65 19.05,3.01
  Bottom 0.406: 19.05,4.28 19.05,3.96 v19.05,3.65
  Bottom 1.27: 19.05,3.96 v19.05,3.65 19.05,3.01
N$22  (via drill 0.9)
  Top 1.27: v16.51,3.65 16.51,3.01
  Bottom 0.406: 16.51,4.28 16.51,3.96 v16.51,3.65
  Bottom 1.27: 16.51,3.96 v16.51,3.65 16.51,3.01
N$23  (via drill 0.9)
  Top 1.27: v16.51,8.73 16.51,9.36
  Bottom 1.27: 16.51,9.36 v16.51,8.73 16.51,8.41
N$24
  Top 0.813: 4.45,43.65 4.45,44.29 4.13,44.6
  Top 1.016: 2.54,44.6 2.54,43.65 | 2.54,44.6 2.54,45.55 | 2.54,44.6 4.13,44.6 | 4.45,43.65 4.45,45.55
N$26
  Top 1.016: 6.35,43.65 6.35,45.55 7.62,44.6 8.89,45.55 8.89,43.65
N$27
  Top 0.406: IC10.11 100.33,25.23 99.06,23.96 99.06,20.16
N$29  (via drill 0.9)
  Top 1.27: v13.97,3.65 13.97,3.01
  Bottom 1.27: 13.97,3.96 v13.97,3.65 13.97,3.01
N$33
  Bottom 0.406: IC12.12 101.6,1.1 111.76,1.1 112.39,1.74 112.39,34.12 111.12,35.4 IC10.1
N$34
  Top 0.406: IC12.4 102.87,11.27 104.14,12.54 104.14,30.32 106.68,32.86 106.68,44.29 107.95,45.55 | 107.95,45.55 IC9.2 | 107.95,45.55 111.12,45.55 112.39,46.83 112.39,62.06 110.49,63.97 20.32,63.97 19.05,62.7 IC1.6
N$35
  Top 0.406: IC9.1 NT.1
  Top 1.27: NT.1 105.41,61.43 104.78,61.43 104.78,53.81 108.58,53.81 108.58,61.43 105.73,61.43 105.73,54.45 107.63,54.45 107.63,60.8 106.68,60.8 106.68,54.13
  Bottom 0.406: R3.1 90.81,52.54 106.05,52.54 IC9.1
N$36  (via drill 0.8)
  Top 0.406: IC12.15 107.95,3.65 106.68,4.92 v106.68,30.32
  Top 1.27: 106.36,30.32 v106.68,30.32 107,30.32
  Bottom 0.406: 106.36,30.32 106.05,30.32 105.41,29.68 99.69,29.68 IC10.10
  Bottom 1.27: v106.68,30.32 106.36,30.32 107,30.32
N$37  (via drill 0.9)
  Top 0.406: 87.63,16.66 87.63,30.32 85.09,32.86 85.09,48.09 83.82,49.37 83.82,54.45 v85.09,55.72 | 46.99,56.03 IC5.11 | v46.99,56.35 50.16,59.52 50.16,61.43 IC5.3 | IC1.11 24.13,51.91 IC2.3 26.67,46.83 24.13,44.29 IC2.11
  Top 1.27: 87.63,16.66 v87.63,16.35 | 85.09,56.03 v85.09,55.72 85.09,55.4 | 46.99,56.67 v46.99,56.35 46.99,56.03
  Bottom 0.406: IC11.15 106.68,16.35 87.95,16.35 | v85.09,55.72 80.64,60.16 51.44,60.16 IC5.3 | IC1.11 26.04,56.35 46.67,56.35
  Bottom 1.27: v46.99,56.35 46.67,56.35 47.31,56.35 | 84.77,55.72 v85.09,55.72 85.41,55.72 | 87.31,16.35 v87.63,16.35 87.95,16.35
N$38  (via drill 0.9)
  Top 0.406: IC11.5 101.6,23.96 101.6,41.74 100.33,43.02 95.25,43.02 93.98,44.29 93.98,49.37 92.71,50.63 v86.36,50.63
  Top 1.27: 86.36,50.95 v86.36,50.63 86.36,50.32
  Bottom 0.406: 86.04,50.63 79.38,50.63 78.74,51.27 78.74,55.72 78.11,56.35 61.59,56.35 IC6.9
  Bottom 1.27: v86.36,50.63 86.04,50.63 86.68,50.63
N$39  (via drill 0.9)
  Top 0.406: IC11.7 v97.79,25.23 99.06,26.51 99.06,32.86 97.79,34.12 IC10.5
  Top 1.27: 97.79,25.55 v97.79,25.23 97.79,24.92
  Bottom 0.406: v97.79,25.23 98.42,25.87 100.97,25.87 IC10.12
  Bottom 1.27: 97.47,25.23 v97.79,25.23 98.11,25.23
N$40  (via drill 0.9)
  Top 0.406: 40.01,30 40.01,30.32 39.37,30.95 IC5.8
  Top 1.27: v40.01,29.68 40.01,30 40.01,29.36
  Bottom 0.406: IC10.9 93.34,29.68 40.32,29.68
  Bottom 1.27: 39.69,29.68 v40.01,29.68 40.32,29.68
N$41  (via drill 0.9)
  Top 0.406: IC10.2 104.14,36.66 104.14,43.02 102.87,44.29 97.79,44.29 96.52,45.55 96.52,49.37 92.71,53.18 v85.09,53.18 | v48.26,60.16 43.81,60.16 IC5.6
  Top 1.27: 85.09,53.49 v85.09,53.18 85.09,52.86 | 48.26,60.48 v48.26,60.16 48.26,59.84
  Bottom 0.406: v85.09,53.18 79.38,58.89 49.53,58.89 v48.26,60.16
  Bottom 1.27: 47.94,60.16 v48.26,60.16 48.58,60.16 | 84.77,53.18 v85.09,53.18 85.41,53.18
N$42
  Bottom 0.406: IC10.3 100.97,37.3 54.61,37.3 | 54.61,37.3 IC7.20 | IC3.9 22.23,32.22 34.92,32.22 40.01,37.3 54.61,37.3
N$43
  Top 0.406: IC10.4 IC9.12
N$44  (via drill 0.9)
  Top 0.406: 93.98,13.49 93.98,23.96 96.52,26.51 96.52,32.86 95.25,34.12 IC10.6
  Top 1.27: v93.98,13.17 93.98,13.49 93.98,12.85
  Bottom 0.406: D1.C 84.45,13.17 93.66,13.17
  Bottom 1.27: v93.98,13.17 93.66,13.17 94.3,13.17
N$45  (via drill 0.9)
  Top 0.406: 109.86,32.54 109.86,37.3 107.95,39.2 IC9.15
  Top 1.27: v109.86,32.22 109.86,32.54 109.86,31.9
  Bottom 0.406: IC9.15 107.95,43.02 106.68,44.29 106.68,50 105.41,51.27 92.08,51.27 R4.1 | C2.1 85.72,30.95 102.87,30.95 104.14,32.22 109.54,32.22
  Bottom 1.27: v109.86,32.22 109.54,32.22 110.17,32.22
N$46  (via drill 0.9)
  Top 0.406: C3.1 83.82,46.51 v83.82,46.83
  Top 1.27: 83.82,47.14 v83.82,46.83 83.82,46.51
  Bottom 0.406: IC9.7 93.34,46.19 90.81,46.19 R5.1 84.14,46.83
  Bottom 1.27: 83.5,46.83 v83.82,46.83 84.14,46.83
N$47
  Top 0.406: LED1.A 95.25,62.06 95.25,54.45 R2.1
N$50  (via drill 0.9)
  Top 0.406: 45.72,47.78 45.72,51.91 45.09,52.54 43.81,52.54 IC5.9
  Top 1.27: v45.72,47.46 45.72,47.78 45.72,47.14
  Bottom 0.406: IC9.11 97.79,41.11 95.25,43.65 73.03,43.65 72.39,44.29 72.39,46.83 71.75,47.46 46.04,47.46
  Bottom 1.27: 45.4,47.46 v45.72,47.46 46.04,47.46
N$51  (via drill 0.9)
  Top 0.406: 74.93,40.16 74.93,44.6 v74.93,44.92
  Top 1.27: v74.93,39.84 74.93,40.16 74.93,39.52 | 74.93,45.24 v74.93,44.92 74.93,44.6
  Bottom 0.406: IC9.4 99.69,44.92 75.25,44.92 v74.93,44.92 | 74.61,39.84 37.47,39.84 34.29,36.66 IC3.1 29.84,34.76 16.51,34.76 3.81,22.06 3.81,16.35 5.71,14.44 D2.2
  Bottom 1.27: 75.25,39.84 v74.93,39.84 74.61,39.84 | 74.61,44.92 v74.93,44.92 75.25,44.92
N$52  (via drill 0.9)
  Top 0.406: IC3.11 24.13,33.17 v24.13,33.49
  Top 1.27: 24.13,33.81 v24.13,33.49 24.13,33.17
  Bottom 0.406: IC9.3 105.41,44.29 106.68,43.02 106.68,39.2 106.05,38.57 38.73,38.57 33.66,33.49 24.45,33.49 v24.13,33.49
  Bottom 1.27: 23.81,33.49 v24.13,33.49 24.45,33.49
N$53  (via drill 0.9)
  Top 0.406: 54.61,57.94 IC5.1 | IC5.13 52.07,55.08 v54.61,57.62
  Top 1.27: v54.61,57.62 54.61,57.94 54.61,57.3
  Bottom 0.406: R2.2 80.01,56.35 78.74,57.62 54.93,57.62 v54.61,57.62 | 54.29,57.62 26.04,57.62 IC1.5
  Bottom 1.27: v54.61,57.62 54.29,57.62 54.93,57.62
N$54  (via drill 0.9)
  Top 0.406: IC3.6 17.78,37.94 17.78,55.72 IC1.4 | v44.45,58.89 IC5.10
  Top 1.27: 44.13,58.89 v44.45,58.89 44.77,58.89
  Bottom 0.406: v44.45,58.89 44.13,58.89 27.3,58.89 IC1.4
  Bottom 1.27: 44.77,58.89 v44.45,58.89 44.13,58.89
N$57
  Top 0.406: IC1.3 20.32,55.72 20.32,35.4 17.78,32.86 17.78,17.62 IC4.11
N$58  (via drill 0.9)
  Top 0.406: v57.15,44.92 57.15,44.6 IC7.21
  Top 1.27: 57.15,45.24 v57.15,44.92 57.15,44.6
  Bottom 0.406: IC1.8 17.78,53.18 17.78,47.46 20.32,44.92 56.83,44.92 v57.15,44.92
  Bottom 1.27: 57.47,44.92 v57.15,44.92 56.83,44.92
N$59  (via drill 0.9)
  Top 0.406: v62.23,46.19 62.23,45.87 IC7.23
  Top 1.27: 62.23,46.51 v62.23,46.19 62.23,45.87
  Bottom 0.406: IC2.6 22.23,46.19 61.91,46.19
  Bottom 1.27: v62.23,46.19 61.91,46.19 62.55,46.19
N$60  (via drill 0.9)
  Top 0.406: 72.39,41.43 IC7.2
  Top 1.27: v72.39,41.11 72.39,41.43 72.39,40.79
  Bottom 0.406: IC2.8 18.41,39.84 33.02,39.84 34.29,41.11 72.07,41.11 v72.39,41.11
  Bottom 1.27: 72.71,41.11 v72.39,41.11 72.07,41.11
N$62
  Bottom 0.406: IC3.3 IC3.4 IC3.5
N$64
  Bottom 0.406: IC3.8 15.88,29.05 10.79,23.96 D4.1 D3.1
N$66
  Bottom 0.406: IC4.7 16.51,25.23 15.88,25.87 13.97,25.87 12.7,24.6 12.7,22.06 16.51,18.25 27.3,18.25 IC4.15
N$68
  Top 0.305: 40.01,18.25 40.01,19.52
N$69
  Top 0.305: 39.37,18.89 40.64,18.89
N$70
  Top 0.305: 40.01,23.33 38.73,23.33
N$71
  Top 0.305: 36.51,22.06 36.51,22.7 37.47,22.7 | 37.47,22.7 38.42,22.7 38.42,22.06 | 37.47,22.7 37.47,23.65
N$72
  Top 1.27: 36-NMI.1 31.75,3.01
  Bottom 0.406: 31.75,3.96 31.75,4.92 31.11,5.55 12.7,5.55 6.99,11.27 6.99,16.35 5.71,17.62 D2.1
  Bottom 1.27: 31.75,3.01 36-NMI.1 31.75,3.96
N$73
  Top 0.305: 37.47,22.06 37.15,22.06 37.15,21.74 37.78,21.74 37.78,22.06 37.47,22.06 | 37.47,22.06 37.47,21.11
RAMDIS
  Top 1.27: 45-RAMDIS.1 19.05,9.36
  Bottom 0.406: D3.2 8.26,13.17 9.53,11.9 17.14,11.9 19.05,10 19.05,9.36
  Bottom 1.27: 45-RAMDIS.1 19.05,9.36 19.05,8.41
RD  (via drill 0.9)
  Top 0.406: IC8.20 54.61,17.62 55.88,18.89 55.88,28.09 | 37.47,28.73 37.47,42.06 | 59.69,42.06 IC7.22
  Top 1.27: 32-RD.1 36.83,3.01 | 37.47,42.7 v37.47,42.38 37.47,42.06 | v37.47,28.41 37.47,28.73 37.47,28.09 | 59.69,42.7 v59.69,42.38 59.69,42.06 | 55.88,28.09 v55.88,28.41 55.88,28.73
  Bottom 0.406: 36.83,3.96 36.83,4.92 37.47,5.55 42.55,5.55 43.18,6.18 43.18,11.27 40.01,14.44 40.01,16.98 41.27,18.25 52.7,18.25 IC8.20 | 55.56,28.41 37.78,28.41 | 37.78,42.38 59.37,42.38
  Bottom 1.27: v55.88,28.41 55.56,28.41 56.2,28.41 | 37.15,28.41 v37.47,28.41 37.78,28.41 | 60.01,42.38 v59.69,42.38 59.37,42.38 | 37.15,42.38 v37.47,42.38 37.78,42.38 | 36.83,3.96 32-RD.1 36.83,3.01
RFSH
  Top 0.406: IC11.6 97.79,21.43 96.52,20.16 96.52,11.27 IC12.6 97.79,8.73 96.52,7.46 96.52,1.74 95.89,1.1 40.64,1.1 39.37,2.38 39.37,3.01
  Top 1.27: 30-RFSH.1 39.37,3.01
  Bottom 1.27: 39.37,3.96 30-RFSH.1 39.37,3.01
ROMDIS
  Top 1.27: 43-ROMDIS.1 21.59,9.36
  Bottom 0.406: D4.2 11.43,13.17 18.41,13.17 21.59,10 21.59,9.36
  Bottom 1.27: 43-ROMDIS.1 21.59,9.36 21.59,8.41
ROMEN  (via drill 0.9)
  Top 0.406: IC9.9 93.98,39.2 93.98,26.51 v92.71,25.23 | 35.56,21.11 35.56,24.28 | v22.86,21.43 22.86,21.11 22.86,13.81 25.4,11.27 25.4,6.18 24.13,4.92 42-ROMEN.1
  Top 1.27: 92.71,25.55 v92.71,25.23 92.71,24.92 | 42-ROMEN.1 24.13,3.01 | 35.56,24.92 v35.56,24.6 35.56,24.28 | v35.56,20.79 35.56,21.11 35.56,20.47 | 22.86,21.74 v22.86,21.43 22.86,21.11
  Bottom 0.406: v92.71,25.23 92.08,24.6 35.88,24.6 | 35.24,20.79 23.5,20.79 v22.86,21.43
  Bottom 1.27: 35.88,20.79 v35.56,20.79 35.24,20.79 | 35.24,24.6 v35.56,24.6 35.88,24.6 | 22.54,21.43 v22.86,21.43 23.18,21.43 | 93.03,25.23 v92.71,25.23 92.39,25.23 | 24.13,3.96 42-ROMEN.1 24.13,3.01
VCC  (via drill 0.9)
  Top 0.406: 33.66,16.35 38.47,12.27 | 38.47,12.27 41.91,9.36 | IC4.16 33.66,16.35 | 33.66,16.35 33.66,29.05 | 33.66,29.05 IC3.14 | 33.66,29.05 33.66,41.74 | 33.66,41.74 IC2.14 | 33.66,49.37 33.66,54.45 | 33.66,41.74 33.66,49.37 | 33.66,54.45 IC1.14 | IC12.16 112.39,2.38 112.39,15.08 | 112.39,15.08 IC11.16 | 112.39,27.78 112.39,15.08 | 112.39,27.78 IC10.14 | IC9.16 112.39,40.48 112.39,27.78 | 33.66,54.45 C11.2 | R3.2 R4.2 R5.2 C4.1 80.01,35.71 | IC7.28 IC8.1 | IC5.14 56.52,52.54 60.96,52.54 | 60.96,52.54 60.96,49.37 59.69,48.09 59.69,45.24 | 69.85,45.87 IC7.26 | 60.96,52.54 60.96,60.16 62.23,61.43 IC6.7 | 33.66,60.16 v34.29,60.8 | 33.66,54.45 33.66,60.16 | 33.66,60.16 31.75,60.16 | 31.75,60.16 IC1.1 | 31.75,60.16 30.48,58.89 30.48,40.48 29.84,39.84 23.5,39.84 22.86,39.2 22.86,35.4 20.32,32.86 20.32,13.81 | IC1.10 21.59,51.91 IC2.4 24.13,46.83 21.59,44.29 IC2.10 | 33.66,49.37 IC2.1 | R1.1 4.45,23.33 11.43,23.33 12.7,22.06 v15.24,22.06 | 20.95,13.81 arc90 20.32,14.44 | 19.68,13.81 arc-90 20.32,14.44 | 20.32,13.81 19.68,13.81 | 20.32,13.81 20.95,13.81 | 20.95,13.81 20.32,14.44 | 19.68,13.81 20.32,14.44 | v38.1,18.89 38.1,12.54 38.42,12.22 38.47,12.27
  Top 1.27: 41.91,9.36 27-VCC.1 | v59.69,44.92 59.69,45.24 59.69,44.6 | 69.85,46.51 v69.85,46.19 69.85,45.87 | v80.01,35.4 80.01,35.71 80.01,35.08 | 15.24,22.38 v15.24,22.06 15.24,21.74
  Bottom 0.406: IC8.27 IC8.28 76.83,16.35 | 76.83,16.35 C1.1 | 76.83,16.35 76.83,13.17 R6.2 79.38,10.63 83.19,10.63 83.82,10 88.9,10 90.81,11.9 95.25,11.9 96.52,13.17 108.58,13.17 IC11.16 | IC9.16 112.39,42.38 112.39,48.73 104.78,56.35 90.17,56.35 88.9,55.08 88.9,50 88.27,49.37 R4.2 78.74,49.37 77.47,50.63 77.47,52.54 | 77.47,52.54 IC6.16 | 29.21,52.54 22.86,52.54 21.59,53.81 IC1.10 | 31.75,52.54 29.21,52.54 | 31.75,52.54 54.61,52.54 | 54.61,52.54 57.15,52.54 | 57.15,52.54 77.47,52.54 | 54.61,52.54 IC5.14 | 57.15,52.54 C10.2 | 79.69,35.4 IC7.28 | 60.01,44.92 66.67,44.92 67.94,46.19 69.53,46.19 | IC5.4 45.09,60.16 34.92,60.16 v34.29,60.8 | 29.21,52.54 IC1.13 | IC1.14 31.75,52.54 | IC2.14 IC2.13 | 15.56,22.06 14.61,22.06 17.14,19.52 28.57,19.52 IC4.16
  Bottom 1.27: 41.91,8.41 27-VCC.1 41.91,9.36 | v80.01,35.4 79.69,35.4 80.33,35.4 | v69.85,46.19 69.53,46.19 70.17,46.19 | 59.37,44.92 v59.69,44.92 60.01,44.92 | 14.92,22.06 v15.24,22.06 15.56,22.06
WR  (via drill 0.9)
  Top 0.406: 80.01,31.9 80.01,23.01 | IC3.12 27.94,27.78 27.94,15.08 34.29,10 33-WR.1
  Top 1.27: 33-WR.1 34.29,9.36 | v80.01,22.7 80.01,23.01 80.01,22.38 | 80.01,32.54 v80.01,32.22 80.01,31.9
  Bottom 0.406: IC11.3 103.5,20.79 92.08,20.79 90.17,22.7 80.33,22.7 | v80.01,32.22 78.11,34.12 72.39,34.12 | 72.39,34.12 40.64,34.12 36.83,30.32 27.94,30.32 IC3.12 | 72.39,34.12 IC7.27
  Bottom 1.27: 34.29,8.41 33-WR.1 34.29,9.36 | 79.69,22.7 v80.01,22.7 80.33,22.7 | 79.69,32.22 v80.01,32.22 80.33,32.22

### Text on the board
Top: - | + | LED | VERD | NEGRE | HARD MICRO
